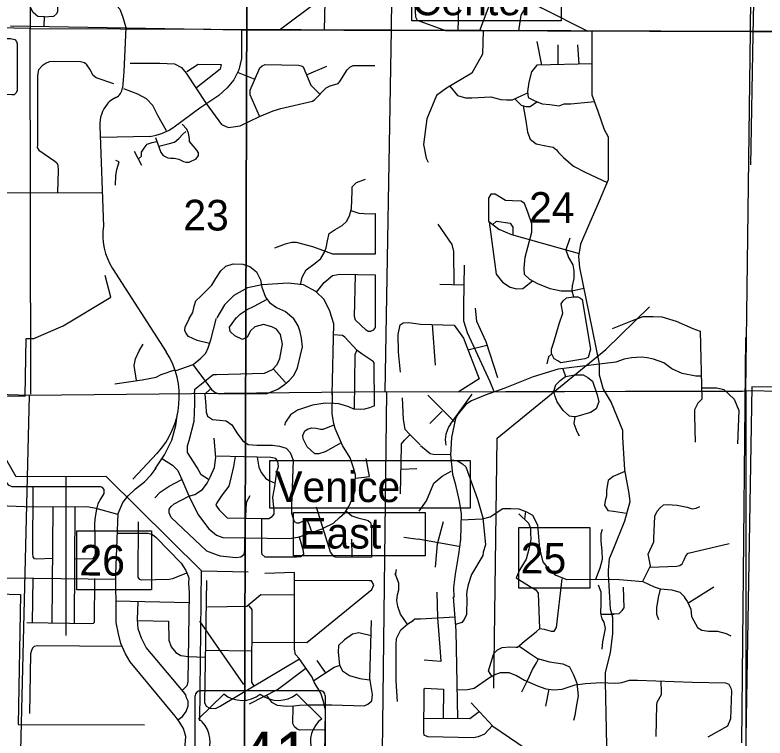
# Model space of a CAD drawing. Extents: x 408847 to 817539, y 923858 to 1151780.
# Drawn here: x 530799 to 541827, y 987614 to 998249 of the extents above; entities that cross this region are included whole.
import ezdxf

# ---------------------------------------------------------------- set-up
doc = ezdxf.new("R2010")
doc.units = 0
for name, color, linetype in [('Cities Incorporated Linear Boundaries', 7, 'Continuous'), ('Level 11', 7, 'Continuous'), ('Level 12', 7, 'Continuous'), ('Level 39', 7, 'Continuous'), ('Level 43', 7, 'Continuous'), ('Local Roads Paved', 7, 'Continuous'), ('Masks for Text', 7, 'Continuous'), ('Narrow River Creek and Branch and Slough', 7, 'Continuous'), ('Quad Borders', 7, 'Continuous'), ('Roadshields US Highways', 7, 'Continuous'), ('Section Lines', 7, 'Continuous'), ('Township  and Range lines', 7, 'Continuous')]:
    doc.layers.add(name, color=color, linetype=linetype)

msp = doc.modelspace()

# ---------------------------------------------------------------- linework, layer by layer
at = {"layer": 'Cities Incorporated Linear Boundaries'}
msp.add_lwpolyline([(552194, 992701), (541635, 992780), (541268, 971566), (562554, 971098)], dxfattribs=at)
at = {"layer": 'Level 12'}
for p, q in [((541485, 987543), (541543, 993503)), ((531546, 991458), (531546, 989123)), ((533539, 990073), (534225, 990058)), ((533510, 989333), (534157, 988400))]:
    msp.add_line(p, q, dxfattribs=at)
at = {"layer": 'Level 39'}
msp.add_lwpolyline([(536636, 998801), (538830, 998801), (538830, 998165), (536636, 998165)], close=True, dxfattribs=at)
at = {"layer": 'Local Roads Paved'}
for p, q in [((530734, 998088), (534140, 998031)), ((532429, 998065), (532401, 997414)), ((534140, 998031), (541624, 998004)), ((534140, 998031), (541624, 998004)), ((541646, 997958), (541612, 996043)), ((541624, 998004), (546853, 997946)), ((541624, 998004), (546853, 997946)), ((538471, 997857), (538542, 997511)), ((538780, 997808), (538780, 997517)), ((539069, 997808), (539088, 997525)), ((535084, 997367), (535384, 997496)), ((532401, 997414), (532380, 997179)), ((534079, 997404), (534325, 997304)), ((532282, 997036), (532221, 996999)), ((533518, 996878), (533137, 996599)), ((532044, 996613), (532099, 995145)), ((532781, 996462), (532061, 996448)), ((532549, 996246), (532661, 996041)), ((532234, 994520), (533022, 993296)), ((537047, 994290), (537398, 994280)), ((536933, 993697), (536977, 993099)), ((537458, 993324), (537737, 993394)), ((534596, 993042), (534776, 992842)), ((537779, 992857), (537842, 992703)), ((536867, 992658), (537266, 992259)), ((537201, 992230), (537519, 992670)), ((536897, 992242), (537082, 992422)), ((532886, 991801), (532533, 991420)), ((536707, 991573), (536475, 991562)), ((531346, 989304), (531360, 991005)), ((531674, 989308), (531683, 991010)), ((538305, 990952), (538289, 990832)), ((535747, 990540), (535751, 990286)), ((536515, 990566), (536727, 990541)), ((537323, 990431), (536727, 990541)), ((536394, 990011), (536406, 990090)), ((531055, 989308), (531064, 989966)), ((540709, 989607), (541074, 989837)), ((532277, 989630), (533358, 989609)), ((539419, 989434), (539609, 989434)), ((533604, 988908), (534277, 988895)), ((535364, 988579), (535243, 988754)), ((538606, 988083), (538655, 988332))]:
    msp.add_line(p, q, dxfattribs=at)
for points in [[(541675, 1003403), (541714, 1003114), (541733, 1002998), (541695, 1002767), (541695, 1002709), (541724, 1002574), (541743, 1002459), (541646, 997958)], [(535351, 998027), (535364, 998661), (535326, 999020), (535243, 999329), (535113, 999621), (534942, 999842), (534826, 1000030), (534792, 1000188), (534821, 1000380), (534884, 1000511)], [(534687, 998029), (537585, 1000204), (537749, 1000242), (537999, 1000242), (538125, 1000233), (538153, 1000204), (538163, 1000117), (538163, 999809), (538125, 999693), (538009, 999462), (537980, 999307), (537980, 998951), (537631, 998018)], [(537315, 998016), (537335, 998691), (537383, 999076), (537585, 999703), (537624, 999866), (537566, 1000021), (537450, 1000146), (537364, 1000185), (537209, 1000223), (537055, 1000223), (536728, 1000165)], [(531228, 998089), (531235, 998222), (531136, 998227), (531068, 998285), (531021, 998368), (531026, 998686), (531053, 998769), (531089, 998821), (531053, 998941), (531032, 999046), (531026, 999108), (531053, 999145), (531271, 999134), (531402, 999072), (531579, 999145), (531860, 999140), (531860, 998806), (531423, 998801), (531423, 998300), (531407, 998264), (531365, 998227), (531225, 998217)], [(536665, 998640), (536690, 998223), (536711, 998173), (537130, 998020)], [(532265, 998419), (532340, 998336), (532378, 998231), (532428, 998065)], [(538207, 998016), (538240, 998248), (538327, 998383), (538394, 998422), (538423, 998422), (538539, 998354), (539222, 998013)], [(534129, 998032), (534129, 997608), (534092, 997442), (534017, 997296), (533916, 997175), (533796, 997066), (533518, 996878)], [(537682, 998018), (537672, 997673), (537518, 997394), (537142, 997172), (536997, 997066), (536853, 996719), (536805, 996343), (536843, 996141), (536872, 996083)], [(539281, 998012), (539281, 997074), (539371, 996833), (539462, 996563), (539522, 996457), (539522, 996367), (539522, 996066), (539522, 995826), (539386, 995510), (539236, 995164), (539116, 994879), (539086, 994698), (539101, 994533), (539386, 993120), (539386, 992954), (539447, 992744), (539567, 992548), (539732, 992143), (539732, 992037), (539762, 991556), (539822, 991210), (539837, 991090), (539762, 990804), (539597, 990399), (539537, 990248), (539522, 990083), (539522, 990023), (539552, 989512), (539582, 989391), (539582, 989151), (539552, 988865), (539477, 988579), (539477, 988444), (539501, 987261)], [(530371, 997902), (530731, 997902), (530795, 997886), (530819, 997858), (530831, 997826), (530831, 997155), (530831, 997131), (530811, 997099), (530787, 997074), (530751, 997074), (530424, 997083), (530359, 997083)], [(532254, 997234), (531991, 997323), (531950, 997359), (531897, 997453), (531857, 997515), (531821, 997546), (531763, 997560), (531317, 997564), (531259, 997542), (531196, 997502), (531143, 997444), (531129, 997359), (531129, 996341), (531125, 996301), (531147, 996261), (531384, 996100), (531415, 996073), (531428, 996042), (531433, 995962), (531424, 995636)], [(532490, 997538), (532928, 997538), (533145, 997529), (533245, 997475), (533316, 997392), (533612, 996949)], [(533324, 997417), (533491, 997525), (533829, 997521), (533816, 997450), (533466, 997175)], [(534112, 996620), (534392, 996757), (534596, 996837), (534709, 996874), (535172, 996979), (535209, 997008), (535376, 997179), (535435, 997208), (535551, 997241), (535576, 997271), (535685, 997442), (535722, 997479), (535772, 997508), (536089, 997508)], [(534392, 996762), (534258, 997075), (534258, 997112), (534258, 997145), (534400, 997471), (534434, 997500), (534475, 997521), (534967, 997513), (535005, 997500), (535034, 997488), (535151, 997216), (535276, 997091)], [(539281, 997530), (538471, 997510), (538394, 997413), (538356, 997259), (538336, 997124), (538346, 997037), (538433, 996989), (538548, 996941), (538664, 996931), (538799, 996912), (538876, 996941), (538972, 996941), (539318, 996977)], [(533024, 996544), (532899, 996770), (532824, 996920), (532732, 997016), (532603, 997083), (532398, 997162)], [(537193, 997202), (537306, 997066), (537421, 997028), (537518, 997028), (537797, 997047), (537942, 997008), (538028, 996999), (538115, 996999), (538250, 997066), (538339, 997104)], [(533612, 996949), (533833, 996640), (533937, 996595), (534112, 996620)], [(538147, 997015), (538240, 996922), (538308, 996902), (538375, 996902), (538473, 996972)], [(538273, 996912), (538308, 996690), (538336, 996526), (538375, 996420), (538462, 996353), (538606, 996324), (538712, 996305), (538760, 996266), (538789, 996228), (538866, 996151), (539011, 996025), (539184, 995939), (539504, 995785)], [(532866, 996446), (532941, 996225), (532978, 996183), (533045, 996150), (533087, 996141), (533137, 996141), (533208, 996129), (533274, 996095), (533312, 996083), (533358, 996083), (533462, 996133), (533499, 996183), (533499, 996221), (533470, 996262), (533366, 996388), (533366, 996429), (533349, 996509), (533324, 996567), (533258, 996642)], [(532916, 996317), (533053, 996354), (533145, 996379), (533208, 996433), (533266, 996496), (533312, 996534)], [(532615, 996133), (532657, 996171), (532661, 996229), (532699, 996292), (532740, 996350), (532815, 996375), (532885, 996390)], [(532277, 995745), (532282, 995883), (532298, 995974), (532332, 996091), (532282, 996108)], [(534997, 994282), (535022, 994391), (535080, 994499), (535213, 994599), (535297, 994666), (535351, 994758), (535372, 994825), (535393, 994929), (535418, 995033), (535505, 995096), (535610, 995150), (535672, 995213), (535718, 995296), (535747, 995401), (535756, 995655), (535756, 995722), (535822, 995784), (535952, 995835)], [(529652, 995652), (529927, 995665), (530011, 995648), (530207, 995631), (532079, 995636)], [(539163, 994227), (538986, 994185), (538830, 994185), (538670, 994220), (538485, 994295), (538370, 994360), (538289, 994430), (538284, 994525), (538300, 994686), (538400, 995052), (538400, 995177), (538340, 995347), (538289, 995478), (538239, 995508), (538114, 995513), (538009, 995518), (537924, 995573), (537859, 995613), (537794, 995613), (537759, 995553), (537759, 995217), (537914, 995097), (538099, 995022), (539093, 994743)], [(535739, 995371), (535856, 995334), (535935, 995330), (536048, 995325), (536093, 995330), (536093, 994729), (535472, 994733), (535180, 994841), (534938, 994900), (534867, 994900), (534771, 994879), (534613, 994821)], [(537017, 995172), (537223, 994871), (537248, 994771), (537253, 994284)], [(537770, 995208), (537874, 994435), (537969, 994320), (538079, 994245), (538174, 994220), (538264, 994225), (538406, 994339)], [(537823, 995167), (537879, 995217), (538079, 995187), (538119, 995127), (538119, 995016)], [(538956, 994966), (538896, 994796), (538936, 994681), (539001, 994576), (539016, 994485), (539016, 994375), (538991, 994265), (538986, 994190), (539011, 994104), (539076, 994104), (539116, 994084), (539136, 994064), (539261, 993333), (539226, 993212), (539176, 993192), (538825, 993132), (538780, 993162), (538725, 993192), (538685, 993268), (538685, 993333), (538720, 993438), (538800, 993704), (538856, 993864), (538830, 993999), (538861, 994044), (538906, 994089), (539011, 994104)], [(533362, 993783), (533412, 993871), (533433, 993967), (533458, 994046), (533533, 994113), (533691, 994276), (533750, 994372), (533825, 994488), (533900, 994555), (534008, 994589), (534150, 994584), (534254, 994551), (534350, 994472), (534409, 994351), (534429, 994246), (534484, 994096), (534542, 994021), (534646, 993946), (534776, 993888), (534897, 993783)], [(537403, 994571), (537393, 993969), (537393, 993749), (537448, 993579), (537779, 992857)], [(535234, 994174), (535343, 994316), (535468, 994416), (535576, 994437), (536093, 994428), (536093, 993652), (536064, 993615), (536027, 993594), (535993, 993594), (535960, 993615), (535806, 993761), (535789, 993815), (535806, 994420)], [(535464, 992665), (535485, 993704), (535430, 993892), (535347, 994063), (535222, 994184), (535042, 994280), (534813, 994305), (534434, 994280), (534217, 994234), (534017, 994125), (533879, 993984), (533766, 993792)], [(534029, 993771), (534108, 993850), (534213, 993917), (534313, 993967), (534506, 994068)], [(537566, 993937), (537585, 993744), (537720, 993445), (537893, 992915)], [(533154, 993017), (533420, 993109), (533529, 993201), (533604, 993276), (533641, 993355), (533679, 993472), (533758, 993776), (533762, 993789)], [(533661, 993417), (533479, 993459), (533349, 993518), (533316, 993564), (533295, 993610), (533299, 993660), (533328, 993714), (533366, 993789)], [(533416, 993109), (533687, 992742), (533741, 992696), (533800, 992675), (534505, 992679), (534663, 992746), (534763, 992813), (534830, 992871), (534897, 992946), (534951, 993059), (534997, 993247), (535026, 993368), (535013, 993493), (534992, 993589), (534963, 993676), (534892, 993789)], [(533437, 992671), (533445, 992746), (533712, 992963), (533762, 992963), (534467, 992980), (534584, 993034), (534655, 993109), (534692, 993196), (534730, 993409), (534701, 993547), (534642, 993626), (534575, 993664), (534454, 993697), (534325, 993660), (534263, 993605), (534213, 993509), (534146, 993476), (534033, 993530), (533962, 993593), (533954, 993655), (534058, 993801)], [(536465, 992994), (536440, 993290), (536435, 993549), (536460, 993691), (536506, 993720), (536590, 993724), (536761, 993703)], [(539582, 993636), (539877, 993756), (540033, 993816), (540183, 993816), (540308, 993811), (540518, 993746), (540764, 993636), (540874, 993596), (540899, 992598), (540839, 992538), (540789, 992443), (540789, 992353), (540799, 991967)], [(536761, 993703), (537258, 993686), (537392, 993494), (537624, 992896), (537315, 992703)], [(536085, 992498), (536081, 993132), (536064, 993153), (535902, 993262), (535831, 993312), (535651, 993508), (535614, 993533), (535480, 993545)], [(532586, 992871), (532553, 993092), (532569, 993192), (532624, 993309), (532682, 993409)], [(535793, 992452), (535802, 993257), (535827, 993316)], [(540894, 992934), (540809, 992934), (540609, 992974), (540458, 993044), (540338, 993134), (540188, 993184), (540093, 993204), (540013, 993214), (539862, 993204), (539757, 993184), (539632, 993144), (539271, 993099), (538785, 993039), (538420, 992924), (537999, 992758), (537713, 992658), (537513, 992573), (537428, 992518), (537313, 992382), (537278, 992312), (537218, 992032), (537203, 991776)], [(538688, 993262), (538645, 993219), (538620, 993119)], [(532269, 992821), (532670, 992884), (532874, 992921), (532949, 992963), (533150, 993030)], [(538856, 993044), (538891, 992929), (539031, 992954), (539151, 992954), (539221, 992919), (539291, 992863), (539361, 992663), (539381, 992558), (539346, 992458), (539261, 992402), (539061, 992342), (539011, 992337), (538951, 992347), (538861, 992433), (538770, 992558), (538740, 992638), (538720, 992718), (538750, 992808), (538815, 992874), (538891, 992929)], [(533670, 992746), (533592, 992673), (533603, 992506), (533609, 992405), (533631, 992350), (533704, 992299), (533810, 992288), (533904, 992277), (533988, 992221), (534071, 992088), (534150, 991987), (534228, 991931), (534356, 991920), (534584, 991920), (534690, 991909), (534785, 991876), (534846, 991814), (534891, 991703), (534863, 991028)], [(540895, 992764), (541120, 992764), (541220, 992739), (541295, 992669), (541375, 992598), (541440, 992433), (541420, 991942)], [(532970, 991721), (533116, 991629), (533191, 991550), (533253, 991416), (533370, 991141), (533499, 990891), (533650, 990690), (533762, 990599), (533854, 990561), (534830, 990548), (534963, 990569), (535314, 990690), (535330, 990699), (535480, 990774), (535572, 990857), (535647, 990928), (535706, 991020), (535756, 991128), (535802, 991254), (535802, 991366), (535806, 991487), (535776, 991587), (535726, 991733), (535614, 991917), (535505, 992167), (535489, 992238), (535464, 992384), (535468, 992685)], [(533645, 991416), (533537, 991487), (533479, 991592), (533337, 991813), (533333, 991913), (533362, 991988), (533433, 992276), (533441, 992530), (533445, 992693)], [(536494, 992617), (536506, 992300), (536531, 992158), (536602, 992079), (536757, 991928)], [(536085, 992501), (536010, 992468), (535939, 992451), (535872, 992447), (535781, 992451), (535706, 992485), (535643, 992505), (535560, 992530), (535489, 992535), (535359, 992539), (535172, 992510), (534951, 992434), (534851, 992368), (534776, 992259), (534763, 992209)], [(532861, 991571), (532999, 991779), (533103, 991996), (533166, 992213), (533188, 992385)], [(539031, 992339), (539016, 992242), (539061, 992122), (539096, 992057)], [(535597, 991956), (535359, 991821), (535264, 991796), (535209, 991796), (535093, 991896), (535034, 992013), (535030, 992063), (535059, 992130), (535109, 992163), (535163, 992176), (535226, 992172), (535293, 992159), (535330, 992159), (535493, 992220)], [(536469, 991203), (536481, 991909), (536481, 991942), (536527, 991996), (536606, 992075)], [(534175, 990561), (534171, 990377), (534163, 990306), (534121, 990273), (534046, 990265), (533821, 990290), (533762, 990306), (533620, 990361), (533095, 990857), (533066, 990924), (533066, 990982), (533095, 991020), (533141, 991058), (533353, 991170), (533445, 991195), (533554, 991270), (533625, 991362), (533670, 991450), (533733, 991592), (533754, 991738), (533729, 992026)], [(536762, 991916), (536902, 991801), (536947, 991791), (537203, 991786)], [(534035, 991753), (534012, 991608), (533975, 991462), (533941, 991320), (533846, 991191), (533766, 991074), (533754, 991037), (533800, 990970), (533916, 990853), (534421, 990841)], [(534429, 990841), (534530, 990841), (534580, 990874), (534609, 990907), (534609, 990957), (534592, 991158), (534617, 991312), (534650, 991533), (534671, 991608), (534663, 991683), (534634, 991725), (534559, 991742), (533766, 991759)], [(534361, 991746), (534384, 991600), (534417, 991517), (534488, 991433), (534534, 991400), (534625, 991363)], [(535810, 991437), (536010, 991462), (535960, 991725)], [(537203, 991779), (537233, 991493), (537273, 991358), (537328, 991097), (537358, 990912), (537348, 990536), (537318, 990316), (537273, 990025), (537248, 989829), (537253, 989679)], [(537223, 991704), (537303, 991689), (537378, 991649), (537428, 991604), (537598, 991127), (537678, 990852), (537718, 990456), (537683, 990346), (537678, 990296), (537513, 990020), (537463, 989865), (537443, 989774), (537438, 989719), (537443, 989664)], [(532282, 990028), (532315, 990917), (532386, 991076), (532461, 991176), (532569, 991280), (532703, 991380), (532803, 991485), (532874, 991581)], [(536742, 990952), (536847, 991102), (536957, 991363), (537082, 991463), (537213, 991538)], [(539766, 991533), (539592, 991458), (539522, 991403), (539497, 991258), (539497, 991173), (539477, 991102), (539467, 991037), (539517, 990962), (539597, 990952), (539792, 990919)], [(530655, 991396), (530696, 991338), (530750, 991315), (532056, 991315), (532078, 991302), (532105, 991270), (532105, 991208), (532060, 991136), (532015, 991059), (531997, 990979), (531979, 990866), (531970, 990776), (531979, 990318), (531961, 990278), (531939, 990247), (531907, 990242), (531683, 990247)], [(532857, 991149), (532932, 991229), (533066, 991316), (533254, 991415)], [(531351, 990256), (531118, 990242), (531086, 990251), (531068, 990278), (531059, 990327), (531068, 991315)], [(534192, 990846), (534200, 991007), (534208, 991091), (534258, 991183)], [(532311, 990902), (531993, 990992), (531854, 991014), (531068, 991010), (530687, 991023), (530610, 991046), (530543, 991077), (530489, 991122), (530449, 991167)], [(534865, 991027), (534866, 990919), (534882, 990855), (534905, 990797), (534939, 990779), (534976, 990777), (535033, 990804), (535074, 990818), (535095, 990809), (535112, 990775), (535161, 990636)], [(535665, 990956), (535751, 990882), (535839, 990853), (535939, 990828), (535993, 990811), (536027, 990786), (536043, 990724), (536039, 990273), (535535, 990269), (535489, 990281), (535468, 990311), (535439, 990348), (535234, 991007)], [(537353, 990822), (537673, 990837), (537784, 990867), (537974, 990992), (538089, 990992), (538209, 990987), (538320, 990942), (538410, 990892), (538480, 990747), (538510, 990396), (538560, 990205), (538660, 990085), (538750, 990010), (538911, 989945), (539462, 989950), (539687, 989945), (540028, 989915), (540198, 989839), (540283, 989809), (540458, 989794), (540574, 989759), (540654, 989679)], [(540028, 989920), (540143, 990145), (540108, 990316), (540133, 990371), (540193, 990501), (540193, 990546), (540208, 990877), (540243, 990952), (540278, 990997), (540333, 991042), (540388, 991047), (540534, 991037), (540684, 991007), (540754, 990987), (540814, 990997), (540869, 991017)], [(538209, 990912), (538350, 990772), (538380, 990701), (538380, 990631), (538385, 990536), (538355, 990391), (538315, 990245), (538224, 990090), (538169, 989971), (538365, 989846), (538455, 989791), (538490, 989745), (538510, 989224)], [(532611, 990792), (532607, 989978), (532624, 989949), (532665, 989941), (533066, 989949), (533120, 989958), (533324, 990045)], [(534978, 990575), (535038, 990369), (535042, 990315), (535001, 990277), (534938, 990273), (534475, 990273), (534434, 990311), (534429, 990340), (534429, 990841)], [(536982, 990125), (537012, 990471), (537097, 990797)], [(532311, 990625), (532753, 990625), (532820, 990608), (532874, 990563), (533241, 990187), (533312, 990079), (533324, 990045)], [(539341, 989950), (539401, 990115), (539437, 990245), (539432, 990361), (539417, 990516), (539417, 990621), (539437, 990686)], [(540143, 990125), (540523, 990140), (540574, 990150), (540609, 990175), (540639, 990235), (540664, 990291), (540699, 990331), (541300, 990476)], [(529852, 990103), (529865, 990016), (529877, 989982), (532271, 989950)], [(531970, 989959), (531961, 989313), (531948, 989299), (531912, 989295), (530974, 989308)], [(533293, 987383), (533312, 987636), (533278, 987753), (533212, 987857), (533153, 987936), (532490, 988733), (532423, 988850), (532353, 989004), (532319, 989146), (532286, 989313), (532286, 989401), (532282, 990039)], [(533324, 990045), (533353, 989968), (533349, 989893), (533358, 989751), (533341, 988445), (533324, 988383), (533270, 988328), (533258, 988312)], [(535353, 987373), (535364, 988024), (535334, 988153), (535297, 988274), (535197, 988437), (535168, 988508), (534976, 988783), (534922, 988842), (534909, 988921), (534909, 990047), (534471, 990035)], [(536573, 989280), (536469, 989434), (536427, 989547), (536415, 989634), (536423, 989722), (536444, 989793), (536444, 989889), (536390, 990035)], [(533616, 989931), (533583, 988136), (533608, 988082), (533662, 988053), (533745, 988049), (533804, 988078), (534980, 988777)], [(534277, 989025), (535088, 989021), (536048, 989797), (536077, 989868), (536043, 989926), (536006, 989926), (534909, 989931)], [(537809, 988523), (537759, 988603), (537799, 988729), (537839, 988859), (537894, 988909), (537964, 988944), (538074, 988954), (538164, 988949), (538189, 988949), (538320, 989064), (538460, 989175), (538515, 989225), (538580, 989215), (538680, 989185), (538725, 989185), (538760, 989240), (538845, 989956)], [(539373, 989867), (539412, 989762), (539412, 989598), (539406, 989447), (539425, 989369), (539458, 989316), (539478, 989224), (539439, 989028), (539425, 988923)], [(537002, 989757), (537012, 989381), (537052, 988880), (537062, 988740), (536817, 988760)], [(539582, 989441), (539682, 989446), (539727, 989487), (539757, 989527), (539747, 989832)], [(540283, 989802), (540258, 989682), (540233, 989527), (540233, 989436), (540263, 989356)], [(534909, 989713), (534413, 989718), (534208, 989547), (533629, 989538)], [(537243, 989692), (537283, 989191), (537303, 987902)], [(537443, 989667), (537438, 989431), (537403, 989356), (537368, 989311), (537275, 989285)], [(540639, 989687), (540689, 989617), (540734, 989507), (540744, 989401), (540834, 989241), (540899, 989201), (540994, 989186), (541130, 989186), (541255, 989151), (541325, 989116)], [(533191, 987882), (533262, 987928), (533316, 988003), (533345, 988086), (533345, 988157), (533320, 988207), (533312, 988249), (533278, 988295), (532728, 988946), (532661, 989084), (532611, 989221), (532599, 989355), (532611, 989618)], [(534238, 989559), (534279, 989505), (534275, 988433), (534308, 988387)], [(532607, 989342), (533057, 989330), (533062, 989054), (533095, 988954), (533162, 988871), (533237, 988829), (533349, 988812), (533595, 988804)], [(534496, 988237), (534571, 988141), (534655, 988099), (534796, 988082), (534897, 988086), (534980, 988099), (535084, 988103), (535455, 988103), (535935, 988086), (535989, 988111), (536048, 988161), (536056, 988253), (536018, 988487), (536043, 989342)], [(536423, 988153), (536402, 988453), (536402, 988988), (536410, 989079), (536473, 989205), (536573, 989292), (536652, 989342)], [(536647, 989341), (536677, 989366), (536762, 989366), (537266, 989397)], [(536035, 989117), (535852, 989159), (535760, 989142), (535643, 989059), (535555, 988975), (535551, 988875), (535572, 988687), (535614, 988604), (535718, 988533), (535868, 988491), (536010, 988470)], [(532369, 988960), (531125, 988971), (531079, 988960), (531056, 988937), (531039, 988903), (531028, 988852), (531011, 987976)], [(538206, 988969), (538351, 988870), (538482, 988785), (538659, 988732), (538855, 988706), (538954, 988660), (539013, 988542), (539058, 988418), (539078, 988234), (539052, 988070), (539032, 987946), (539013, 987873)], [(538252, 988293), (538318, 988431), (538338, 988470), (538410, 988621), (538469, 988719), (538495, 988778)], [(534246, 988116), (534659, 988328), (535077, 988639)], [(535193, 988458), (535493, 988658), (535564, 988679)], [(537296, 988323), (537453, 988329), (537548, 988349), (537759, 988494), (537844, 988544), (537939, 988579), (538059, 988579), (538174, 988534), (538289, 988464), (538480, 988379), (538605, 988339), (538720, 988324), (538845, 988334), (539036, 988394), (539186, 988414), (539346, 988424), (539401, 988429), (539627, 988419), (539687, 988424), (539722, 988429), (539832, 988464), (539952, 988464), (540759, 988434)], [(540293, 988449), (540298, 988294), (540298, 988249), (540238, 988138), (540233, 988103), (540223, 987637)], [(540759, 988434), (541245, 988424), (541295, 988404), (541325, 988349), (541335, 988309), (541320, 987898), (541275, 987788), (540984, 987627)], [(537820, 987796), (537702, 987670), (537610, 987631), (537538, 987618), (536869, 987631), (536817, 987657), (536811, 987697), (536817, 988300), (536817, 988339), (536830, 988346), (537099, 988333), (537092, 987904)], [(537505, 988129), (537826, 987788), (538435, 987369)], [(535351, 987736), (534988, 987727), (534947, 987744), (534909, 987778), (534884, 987828), (534888, 988070)], [(536811, 987906), (537486, 987900), (537622, 988006)]]:
    msp.add_lwpolyline(points, dxfattribs=at)
for centre, radius, start, end in [((532205, 997194), 176, 295.8765, 354.922), ((532524, 996631), 480, 140.1323, 182.119), ((532339, 996805), 227, 121.4513, 144.0826), ((532669, 997282), 828, 277.791, 304.3804), ((533002, 995014), 913, 171.7317, 212.7767), ((531986, 992636), 1229, 317.1457, 32.4739), ((537526, 991996), 400, 144.1983, 190.716)]:
    msp.add_arc(centre, radius, start, end, dxfattribs=at)
at = {"layer": 'Masks for Text'}
for points in [[(534546, 991696), (537491, 991696), (537491, 990995), (534546, 990995)], [(534896, 990933), (536832, 990933), (536832, 990294), (534896, 990294)], [(531706, 990659), (532807, 990659), (532807, 989794), (531706, 989794)], [(538205, 990711), (539253, 990711), (539253, 989820), (538205, 989820)]]:
    msp.add_lwpolyline(points, close=True, dxfattribs=at)
at = {"layer": 'Narrow River Creek and Branch and Slough'}
for p, q in [((532210, 994099), (532125, 994419)), ((531506, 993679), (532210, 994099)), ((539488, 993327), (540130, 993955)), ((531078, 993490), (531506, 993679)), ((530947, 992643), (530964, 993489)), ((530964, 993489), (531078, 993490)), ((537888, 992026), (539488, 993327)), ((530554, 992649), (530947, 992643)), ((530815, 991455), (530229, 992478)), ((537841, 988348), (537888, 992026)), ((532138, 991462), (530815, 991455)), ((533539, 990073), (532138, 991462)), ((533518, 987868), (533539, 990073)), ((528213, 989782), (530878, 989726)), ((530878, 989726), (530847, 987814)), ((530847, 987814), (532701, 987809))]:
    msp.add_line(p, q, dxfattribs=at)
at = {"layer": 'Quad Borders'}
for p, q in [((534119, 969475), (534254, 1014913)), ((534120, 969762), (534254, 1014913)), ((534254, 1014913), (534120, 969762))]:
    msp.add_line(p, q, dxfattribs=at)
at = {"layer": 'Roadshields US Highways'}
for p, q in [((533524, 988311), (535285, 988311)), ((533449, 986503), (533449, 988236)), ((533869, 988261), (533499, 987895)), ((533869, 988261), (533869, 988261)), ((534405, 988259), (534405, 988259)), ((535310, 987895), (534941, 988261)), ((535360, 988236), (535360, 986503))]:
    msp.add_line(p, q, dxfattribs=at)
for centre, radius, start, end in [((533524, 988236), 75, 90, 180), ((535285, 988236), 75, 0, 90), ((534138, 988597), 430, 231.2915, 308.3626), ((534672, 988597), 430, 231.6374, 308.7085), ((533258, 987565), 409, 338.3056, 53.8199), ((535552, 987565), 409, 126.1801, 201.6944)]:
    msp.add_arc(centre, radius, start, end, dxfattribs=at)
at = {"layer": 'Section Lines'}
for p, q in [((531013, 1003355), (531023, 998052)), ((536336, 998031), (536377, 1003305)), ((531023, 998052), (525668, 998119)), ((531034, 992673), (531023, 998052)), ((531023, 998052), (536335, 998031)), ((536244, 992708), (536335, 998031)), ((536336, 998031), (541614, 998010)), ((546853, 997950), (541614, 998010)), ((531007, 992653), (525632, 992791)), ((536244, 992708), (541547, 992720)), ((536260, 992708), (541495, 992715)), ((546749, 992638), (541547, 992720)), ((531007, 992653), (530882, 987430)), ((536260, 992708), (531007, 992653)), ((536260, 992708), (536198, 987411))]:
    msp.add_line(p, q, dxfattribs=at)
at = {"layer": 'Township  and Range lines'}
for p, q in [((541614, 998010), (541654, 1003283)), ((541547, 992720), (541614, 998010)), ((541547, 992720), (541547, 987393))]:
    msp.add_line(p, q, dxfattribs=at)

# ---------------------------------------------------------------- texts
at = {"layer": 'Level 11'}
msp.add_text('Center', height=450, dxfattribs=at).set_placement((536633, 998245))
at = {"layer": 'Level 39'}
for s, p in [('Venice', (534624, 991084)), ('East', (534979, 990401))]:
    msp.add_text(s, height=450, rotation=0, dxfattribs=at).set_placement(p)
at = {"layer": 'Level 43'}
for s, rotation, p in [('24', 359.7207, (538356, 995194)), ('23', 359.6504, (533272, 995082)), ('26', 359.6504, (531745, 990005)), ('25', 359.7207, (538234, 990035))]:
    msp.add_text(s, height=450, rotation=rotation, dxfattribs=at).set_placement(p)
at = {"layer": 'Roadshields US Highways'}
msp.add_text('41', height=680, dxfattribs=at).set_placement((534119, 987029))

doc.saveas('drawing.dxf')
